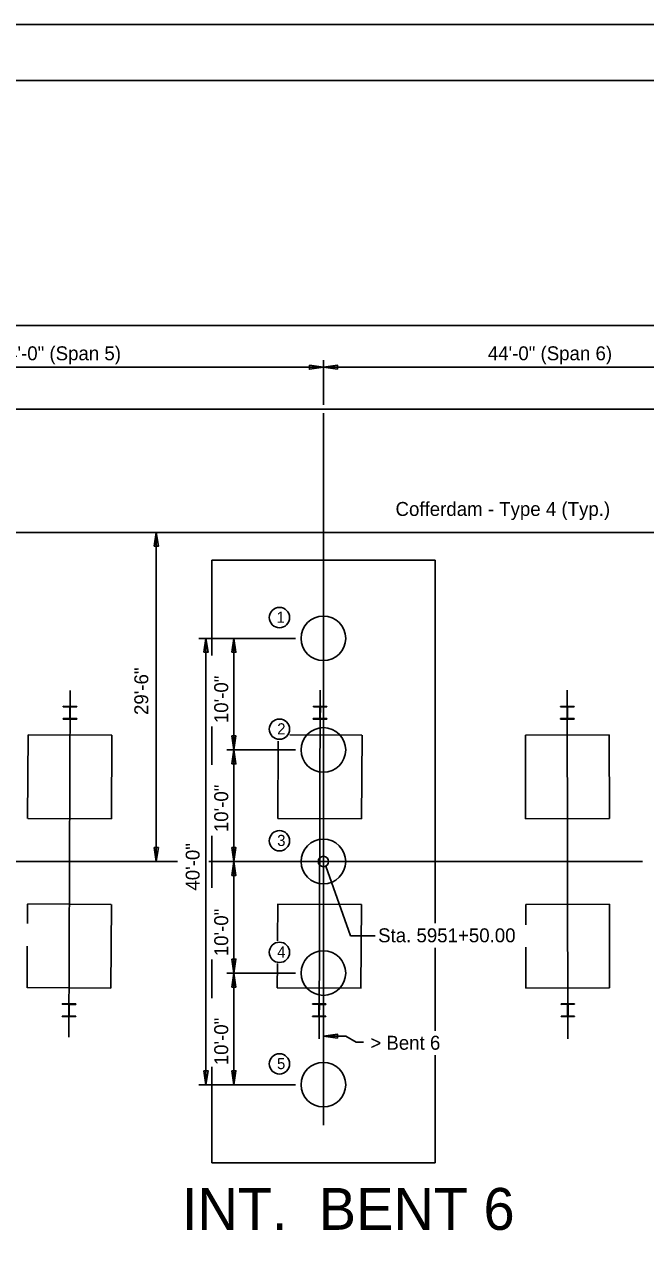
# Model space of a CAD drawing. Extents: x -10371 to -10009, y 1939 to 2167.
# Drawn here: x -10137.7 to -10082, y 2050 to 2159.5 of the extents above; entities that cross this region are included whole.
import ezdxf

# ---------------------------------------------------------------- set-up
doc = ezdxf.new("R2010")
doc.units = 0
for name, color, linetype in [('BR_AUTO DIMENSION', 7, 'Continuous'), ('BR_BORDER LINES', 7, 'Continuous'), ('BR_CENTER LINES', 7, 'Continuous'), ('BR_CONCRETE', 7, 'Continuous'), ('BR_STRUCTURAL STEEL', 7, 'Continuous'), ('BR_TABLE LINES', 7, 'Continuous'), ('BR_TEXT', 7, 'Continuous'), ('RD_SHT_IplotShp', 7, 'Continuous')]:
    doc.layers.add(name, color=color, linetype=linetype)

msp = doc.modelspace()

# ---------------------------------------------------------------- linework, layer by layer
at = {"layer": 'BR_AUTO DIMENSION'}
for p, q in [((-10330.91, 2132.54), (-10036.91, 2132.54)), ((-10350.91, 2128.79), (-10016.91, 2128.79)), ((-10330.91, 2125.04), (-10036.91, 2125.04)), ((-10125.88, 2084.49), (-10125.88, 2113.99)), ((-10113.4, 2104.49), (-10122.06, 2104.49)), ((-10121.44, 2104.49), (-10121.44, 2064.49)), ((-10118.94, 2104.49), (-10118.94, 2104.49)), ((-10118.94, 2104.49), (-10118.94, 2064.49)), ((-10113.4, 2094.49), (-10119.56, 2094.49)), ((-10110.7, 2084.07), (-10108.48, 2077.83)), ((-10108.48, 2077.83), (-10106.27, 2077.83)), ((-10113.4, 2074.49), (-10119.56, 2074.49)), ((-10110.91, 2068.83), (-10108.91, 2068.83)), ((-10108.91, 2068.83), (-10107.97, 2068.29)), ((-10107.97, 2068.29), (-10107.32, 2068.29)), ((-10113.4, 2064.49), (-10122.06, 2064.49)), ((-10118.94, 2064.49), (-10118.94, 2064.49))]:
    msp.add_line(p, q, dxfattribs=at)
for points in [[(-10112.16, 2128.98), (-10110.91, 2128.79), (-10112.16, 2128.6)], [(-10109.66, 2128.6), (-10110.91, 2128.79), (-10109.66, 2128.98)], [(-10126.07, 2112.74), (-10125.88, 2113.99), (-10125.69, 2112.74)], [(-10121.63, 2103.24), (-10121.44, 2104.49), (-10121.25, 2103.24)], [(-10119.13, 2103.24), (-10118.94, 2104.49), (-10118.75, 2103.24)], [(-10119.13, 2095.74), (-10118.94, 2094.49), (-10118.75, 2095.74)], [(-10119.13, 2093.24), (-10118.94, 2094.49), (-10118.75, 2093.24)], [(-10125.69, 2085.74), (-10125.88, 2084.49), (-10126.07, 2085.74)], [(-10119.13, 2085.74), (-10118.94, 2084.49), (-10118.75, 2085.74)], [(-10119.13, 2083.24), (-10118.94, 2084.49), (-10118.75, 2083.24)], [(-10119.13, 2075.74), (-10118.94, 2074.49), (-10118.75, 2075.74)], [(-10119.13, 2073.24), (-10118.94, 2074.49), (-10118.75, 2073.24)], [(-10109.66, 2068.65), (-10110.91, 2068.83), (-10109.66, 2069.02)], [(-10121.63, 2065.74), (-10121.44, 2064.49), (-10121.25, 2065.74)], [(-10119.13, 2065.74), (-10118.94, 2064.49), (-10118.75, 2065.74)]]:
    msp.add_lwpolyline(points, close=True, dxfattribs=at)
msp.add_circle((-10110.91, 2084.49), 0.469, dxfattribs=at)
at = {"layer": 'BR_BORDER LINES'}
for p, q in [((-10370.58, 2159.51), (-10010.58, 2159.51)), ((-10015.58, 2154.49), (-10352.25, 2154.49))]:
    msp.add_line(p, q, dxfattribs=at)
at = {"layer": 'BR_CENTER LINES'}
for p, q in [((-10110.91, 2125.41), (-10110.91, 2129.41)), ((-10110.91, 2060.87), (-10110.91, 2124.66)), ((-10352.25, 2113.99), (-10015.58, 2113.99)), ((-10165.1, 2084.49), (-10123.98, 2084.49)), ((-10121.17, 2084.49), (-10082.33, 2084.49))]:
    msp.add_line(p, q, dxfattribs=at)
at = {"layer": 'BR_CONCRETE'}
for p, q in [((-10137.41, 2088.34), (-10137.36, 2095.84)), ((-10129.87, 2095.8), (-10137.37, 2095.85)), ((-10129.91, 2088.31), (-10129.86, 2095.81)), ((-10115, 2088.34), (-10114.96, 2095.26)), ((-10107.46, 2095.8), (-10113.91, 2095.84)), ((-10107.5, 2088.31), (-10107.45, 2095.81)), ((-10092.8, 2095.82), (-10085.3, 2095.83)), ((-10092.8, 2095.82), (-10092.79, 2088.32)), ((-10085.3, 2095.83), (-10085.29, 2088.33)), ((-10129.9, 2088.3), (-10137.4, 2088.35)), ((-10107.49, 2088.3), (-10114.99, 2088.35)), ((-10092.79, 2088.32), (-10085.29, 2088.33)), ((-10129.93, 2080.63), (-10137.43, 2080.69)), ((-10137.43, 2078.93), (-10137.41, 2080.67)), ((-10129.96, 2073.15), (-10129.91, 2080.65)), ((-10115.02, 2077.39), (-10115, 2080.67)), ((-10107.51, 2080.64), (-10115.01, 2080.68)), ((-10107.55, 2073.15), (-10107.5, 2080.65)), ((-10092.78, 2080.65), (-10085.28, 2080.67)), ((-10092.78, 2080.65), (-10092.78, 2078.8)), ((-10085.28, 2080.67), (-10085.27, 2073.17)), ((-10137.46, 2073.17), (-10137.44, 2076.9)), ((-10092.77, 2076.82), (-10092.77, 2073.15)), ((-10115.05, 2073.17), (-10115.03, 2075.34)), ((-10129.95, 2073.13), (-10137.45, 2073.19)), ((-10107.54, 2073.14), (-10115.04, 2073.18)), ((-10092.77, 2073.15), (-10085.27, 2073.17))]:
    msp.add_line(p, q, dxfattribs=at)
for centre in [(-10110.91, 2104.49), (-10110.91, 2094.49), (-10110.91, 2084.49), (-10110.91, 2074.49), (-10110.91, 2064.49)]:
    msp.add_circle(centre, 2, dxfattribs=at)
at = {"layer": 'BR_STRUCTURAL STEEL'}
for p, q in [((-10133, 2098.39), (-10134.22, 2098.4)), ((-10134.22, 2098.4), (-10134.22, 2098.36)), ((-10134.22, 2098.36), (-10133.69, 2098.35)), ((-10133.63, 2098.29), (-10133.64, 2097.36)), ((-10133.6, 2097.36), (-10133.59, 2098.29)), ((-10133.53, 2098.35), (-10133, 2098.35)), ((-10133, 2098.35), (-10133, 2098.39)), ((-10110.6, 2098.39), (-10111.81, 2098.4)), ((-10111.81, 2098.4), (-10111.81, 2098.36)), ((-10111.81, 2098.36), (-10111.28, 2098.35)), ((-10111.22, 2098.29), (-10111.23, 2097.36)), ((-10111.19, 2097.36), (-10111.18, 2098.29)), ((-10111.13, 2098.35), (-10110.6, 2098.35)), ((-10110.6, 2098.35), (-10110.6, 2098.39)), ((-10089.66, 2098.35), (-10089.66, 2098.39)), ((-10089.66, 2098.39), (-10088.45, 2098.39)), ((-10089.13, 2098.35), (-10089.66, 2098.35)), ((-10089.08, 2097.36), (-10089.08, 2098.29)), ((-10089.03, 2098.29), (-10089.03, 2097.36)), ((-10088.45, 2098.35), (-10088.98, 2098.35)), ((-10088.45, 2098.39), (-10088.45, 2098.35)), ((-10133.7, 2097.3), (-10134.23, 2097.31)), ((-10134.23, 2097.31), (-10134.23, 2097.26)), ((-10134.23, 2097.26), (-10133.01, 2097.26)), ((-10133.01, 2097.3), (-10133.54, 2097.3)), ((-10133.01, 2097.26), (-10133.01, 2097.3)), ((-10111.29, 2097.3), (-10111.82, 2097.31)), ((-10111.82, 2097.31), (-10111.82, 2097.26)), ((-10111.82, 2097.26), (-10110.6, 2097.26)), ((-10110.6, 2097.3), (-10111.13, 2097.3)), ((-10110.6, 2097.26), (-10110.6, 2097.3)), ((-10089.66, 2097.26), (-10089.66, 2097.3)), ((-10089.66, 2097.3), (-10089.13, 2097.3)), ((-10088.45, 2097.26), (-10089.66, 2097.26)), ((-10088.98, 2097.3), (-10088.45, 2097.3)), ((-10088.45, 2097.3), (-10088.45, 2097.26)), ((-10134.31, 2071.69), (-10134.31, 2071.73)), ((-10134.31, 2071.73), (-10133.1, 2071.72)), ((-10133.78, 2071.69), (-10134.31, 2071.69)), ((-10133.73, 2070.69), (-10133.73, 2071.63)), ((-10133.68, 2071.63), (-10133.69, 2070.69)), ((-10133.1, 2071.68), (-10133.63, 2071.68)), ((-10133.1, 2071.72), (-10133.1, 2071.68)), ((-10111.9, 2071.69), (-10111.9, 2071.73)), ((-10111.9, 2071.73), (-10110.68, 2071.72)), ((-10111.37, 2071.69), (-10111.9, 2071.69)), ((-10111.32, 2070.69), (-10111.31, 2071.63)), ((-10111.27, 2071.63), (-10111.28, 2070.69)), ((-10110.68, 2071.68), (-10111.21, 2071.68)), ((-10110.68, 2071.72), (-10110.68, 2071.68)), ((-10088.41, 2071.73), (-10089.62, 2071.73)), ((-10089.62, 2071.73), (-10089.62, 2071.68)), ((-10089.62, 2071.68), (-10089.09, 2071.69)), ((-10089.04, 2071.63), (-10089.03, 2070.69)), ((-10088.99, 2070.69), (-10088.99, 2071.63)), ((-10088.94, 2071.69), (-10088.41, 2071.69)), ((-10088.41, 2071.69), (-10088.41, 2071.73)), ((-10134.32, 2070.6), (-10134.32, 2070.64)), ((-10134.32, 2070.64), (-10133.79, 2070.64)), ((-10133.1, 2070.59), (-10134.32, 2070.6)), ((-10133.63, 2070.63), (-10133.1, 2070.63)), ((-10133.1, 2070.63), (-10133.1, 2070.59)), ((-10111.9, 2070.6), (-10111.9, 2070.64)), ((-10111.9, 2070.64), (-10111.37, 2070.64)), ((-10110.69, 2070.59), (-10111.9, 2070.6)), ((-10111.22, 2070.63), (-10110.69, 2070.63)), ((-10110.69, 2070.63), (-10110.69, 2070.59)), ((-10089.09, 2070.64), (-10089.62, 2070.63)), ((-10089.62, 2070.63), (-10089.62, 2070.59)), ((-10089.62, 2070.59), (-10088.41, 2070.59)), ((-10088.41, 2070.64), (-10088.94, 2070.64)), ((-10088.41, 2070.59), (-10088.41, 2070.64))]:
    msp.add_line(p, q, dxfattribs=at)
for centre, start, end in [((-10133.69, 2098.29), 359.6116, 89.6116), ((-10133.53, 2098.29), 89.6116, 179.6116), ((-10111.28, 2098.29), 359.6368, 89.6368), ((-10111.13, 2098.29), 89.6368, 179.6368), ((-10089.13, 2098.29), 0.0877, 90.0877), ((-10088.98, 2098.29), 90.0877, 180.0877), ((-10133.7, 2097.36), 269.6116, 359.6116), ((-10133.54, 2097.36), 179.6116, 269.6116), ((-10111.29, 2097.36), 269.6368, 359.6368), ((-10111.13, 2097.36), 179.6368, 269.6368), ((-10089.13, 2097.36), 270.0877, 0.0877), ((-10088.98, 2097.36), 180.0877, 270.0877), ((-10133.78, 2071.63), 359.6116, 89.6116), ((-10133.63, 2071.63), 89.6116, 179.6116), ((-10111.37, 2071.63), 359.6368, 89.6368), ((-10111.21, 2071.63), 89.6368, 179.6368), ((-10089.09, 2071.63), 0.0877, 90.0877), ((-10088.94, 2071.63), 90.0877, 180.0877), ((-10133.79, 2070.69), 269.6116, 359.6116), ((-10133.63, 2070.69), 179.6116, 269.6116), ((-10111.37, 2070.69), 269.6368, 359.6368), ((-10111.22, 2070.69), 179.6368, 269.6368), ((-10089.09, 2070.69), 270.0877, 0.0877), ((-10088.94, 2070.69), 180.0877, 270.0877)]:
    msp.add_arc(centre, 0.0569, start, end, dxfattribs=at)
at = {"layer": 'BR_TABLE LINES'}
for p, q in [((-10120.91, 2111.49), (-10100.91, 2111.49)), ((-10120.91, 2102.96), (-10120.91, 2111.49)), ((-10100.91, 2078.95), (-10100.91, 2111.49)), ((-10133.61, 2099.83), (-10133.71, 2068.75)), ((-10111.2, 2099.84), (-10111.3, 2068.59)), ((-10089.06, 2099.86), (-10089.01, 2068.6)), ((-10120.91, 2093.14), (-10120.91, 2096.58)), ((-10120.91, 2082.13), (-10120.91, 2086.79)), ((-10100.91, 2069.3), (-10100.91, 2076.75)), ((-10120.91, 2072.24), (-10120.91, 2075.72)), ((-10100.91, 2057.49), (-10100.91, 2067.13)), ((-10120.91, 2057.49), (-10120.91, 2066.1)), ((-10120.91, 2057.49), (-10100.91, 2057.49))]:
    msp.add_line(p, q, dxfattribs=at)
at = {"layer": 'BR_TEXT'}
for centre in [(-10114.85, 2106.35), (-10114.85, 2096.35), (-10114.85, 2086.35), (-10114.85, 2076.35), (-10114.85, 2066.35)]:
    msp.add_circle(centre, 0.91, dxfattribs=at)
at = {"layer": 'RD_SHT_IplotShp'}
msp.add_lwpolyline([(-10370.58, 2159.49), (-10010.58, 2159.49), (-10010.58, 1939.49), (-10370.58, 1939.49)], close=True, dxfattribs=at)

# ---------------------------------------------------------------- texts
at = {"layer": 'BR_AUTO DIMENSION'}
for s, p in [('44\'-0" (Span 5)', (-10140.18, 2129.41)), ('44\'-0" (Span 6)', (-10096.18, 2129.41))]:
    msp.add_text(s, height=1.25, dxfattribs=at).set_placement(p)
at = {"layer": 'BR_TEXT'}
for s, height, p in [('Cofferdam - Type 4 (Typ.)', 1.25, (-10104.45, 2115.46)), ('1', 1, (-10115.11, 2105.88)), ('2', 1, (-10115.05, 2095.88)), ('3', 1, (-10115.05, 2085.88)), ('Sta. 5951+50.00', 1.25, (-10106.01, 2077.25)), ('4', 1, (-10115.05, 2075.88)), ('> Bent 6', 1.25, (-10106.71, 2067.62)), ('5', 1, (-10115.07, 2065.88))]:
    msp.add_text(s, height=height, dxfattribs=at).set_placement(p)
for s, height, rotation, p in [('29\'-6"', 1.25, 90, (-10126.6, 2097.62)), ('10\'-0"', 1.25, 90, (-10119.44, 2096.89)), ('10\'-0"', 1.25, 90, (-10119.44, 2087.12)), ('40\'-0"', 1.25, 90, (-10122, 2081.88)), ('10\'-0"', 1.25, 90, (-10119.44, 2076)), ('10\'-0"', 1.25, 90, (-10119.44, 2066.23)), ('INT.  BENT 6', 3.75, 360, (-10123.59, 2051.48))]:
    msp.add_text(s, height=height, rotation=rotation, dxfattribs=at).set_placement(p)

doc.saveas('drawing.dxf')
